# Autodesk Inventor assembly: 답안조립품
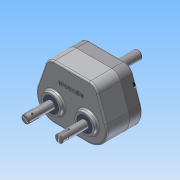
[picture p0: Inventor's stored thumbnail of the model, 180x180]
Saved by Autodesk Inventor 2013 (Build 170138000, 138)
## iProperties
Created: 2014-12
Part Number: 답안조립품
Document SubType Name: Assembly
Designer: Administrator
Author: Administrator
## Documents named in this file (14)
- E:\441209V1043\답안조립품.iam
- E:\441209V1043\본체.ipt
- E:\441209V1043\M 5 x 35.ipt
- E:\441209V1043\멈춤링.ipt
- E:\441209V1043\메인기어.ipt
- E:\441209V1043\메인축.ipt
- E:\441209V1043\베어링- 6202.ipt
- E:\441209V1043\베어링- 6203.ipt
- E:\441209V1043\서브기어.ipt
- E:\441209V1043\서브축.ipt
- E:\441209V1043\오일시일-D-15.ipt
- E:\441209V1043\오일시일-D-17.ipt
- E:\441209V1043\커버.ipt
- E:\441209V1043\키5x5.ipt
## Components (15 placed, 6 different names)
1. KS B 1003 - 미터 M 5 x 35:1
2. KS B 1336 17 x 1:1
3. KS B 2023 6202 - 15 x 35 x 11:1
4. KS B 2023 6203 - 17 x 40 x 12:1
5. KS B 2804 D D - 15 30 7:1
6. KS B 2804 D D - 17 30 8:1
7. KS B 2804 D D - 15 30 7:2
8. KS B 1336 17 x 1:2
9. KS B 1336 17 x 1:3
10. KS B 2023 6203 - 17 x 40 x 12:2
11. KS B 2023 6202 - 15 x 35 x 11:2
12. KS B 2023 6202 - 15 x 35 x 11:3
13. KS B 2023 6202 - 15 x 35 x 11:4
14. KS B 1003 - 미터 M 5 x 35:2
15. KS B 1003 - 미터 M 5 x 35:3
